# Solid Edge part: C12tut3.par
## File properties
Accuracy: 0.990
Author: CADCIM
Template: ansi part.par
Last saved by: CADCIM
Revision: 9
Application: Solid Edge
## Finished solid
Body 1: solid body, 13 faces, 19 edges, 8 vertices.
  Faces by surface: plane 9, cylinder 4
  Edges by curve: line 10, circle 8, ellipse 1
Bounding box of the edges (mm): 31.750 x 82.544 x 31.750, from (-15.875, -77.8163, -15.875) to (15.875, 4.7283, 15.875).
Cylindrical faces by radius (mm): R5.5944 x1, R6.35 x1, R7.9375 x1, R15.875 x1
Planar faces by outward normal: +x 1, +y 1, +z 1, -x 1, -y 4, oblique 1
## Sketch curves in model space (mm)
line (-22.2359, -0.0325, 12.7) -> (-22.2334, -4.7925, 7.935)
line (-22.2322, -77.8163, 5.5531) -> (-22.2323, -0.0289, 5.77)
line (-22.2262, -77.8103, -5.6356) -> (-22.2263, -0.0229, -5.5751)
line (-22.2326, -68.2917, 6.3138) -> (-22.2326, -77.8167, 6.3087)
line (-22.2326, -77.8167, 6.3087) -> (-22.2258, -77.8099, -6.3913)
line (-22.2258, -68.2849, -6.3862) -> (-22.2258, -77.8099, -6.3913)
line (-22.2376, -0.0342, 15.875) -> (-22.2208, -0.0174, -15.875)
line (-22.2376, 4.7283, 15.8775) -> (-22.2376, -0.0342, 15.875)
line (-22.2376, 4.7283, 15.8775) -> (-22.2208, 4.7451, -15.8725)
line (-22.2208, 4.7451, -15.8725) -> (-22.2208, -0.0174, -15.875)
line (-22.225, -0.0216, -7.9375) -> (-22.225, -68.2841, -7.9737)
line (-22.2334, -0.03, 7.9375) -> (-22.2334, -68.2925, 7.9013)
line (-22.2334, -68.2925, 7.9013) -> (-22.225, -68.2841, -7.9737)
line (0, 0, 22.225) -> (0, 0, -22.225)
line (22.225, 0, 0) -> (-22.225, 0, 0)
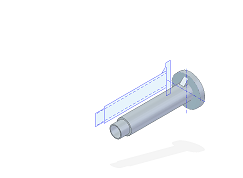
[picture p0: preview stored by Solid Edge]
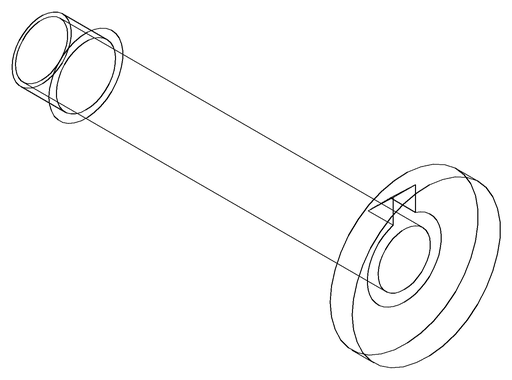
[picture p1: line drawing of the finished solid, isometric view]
